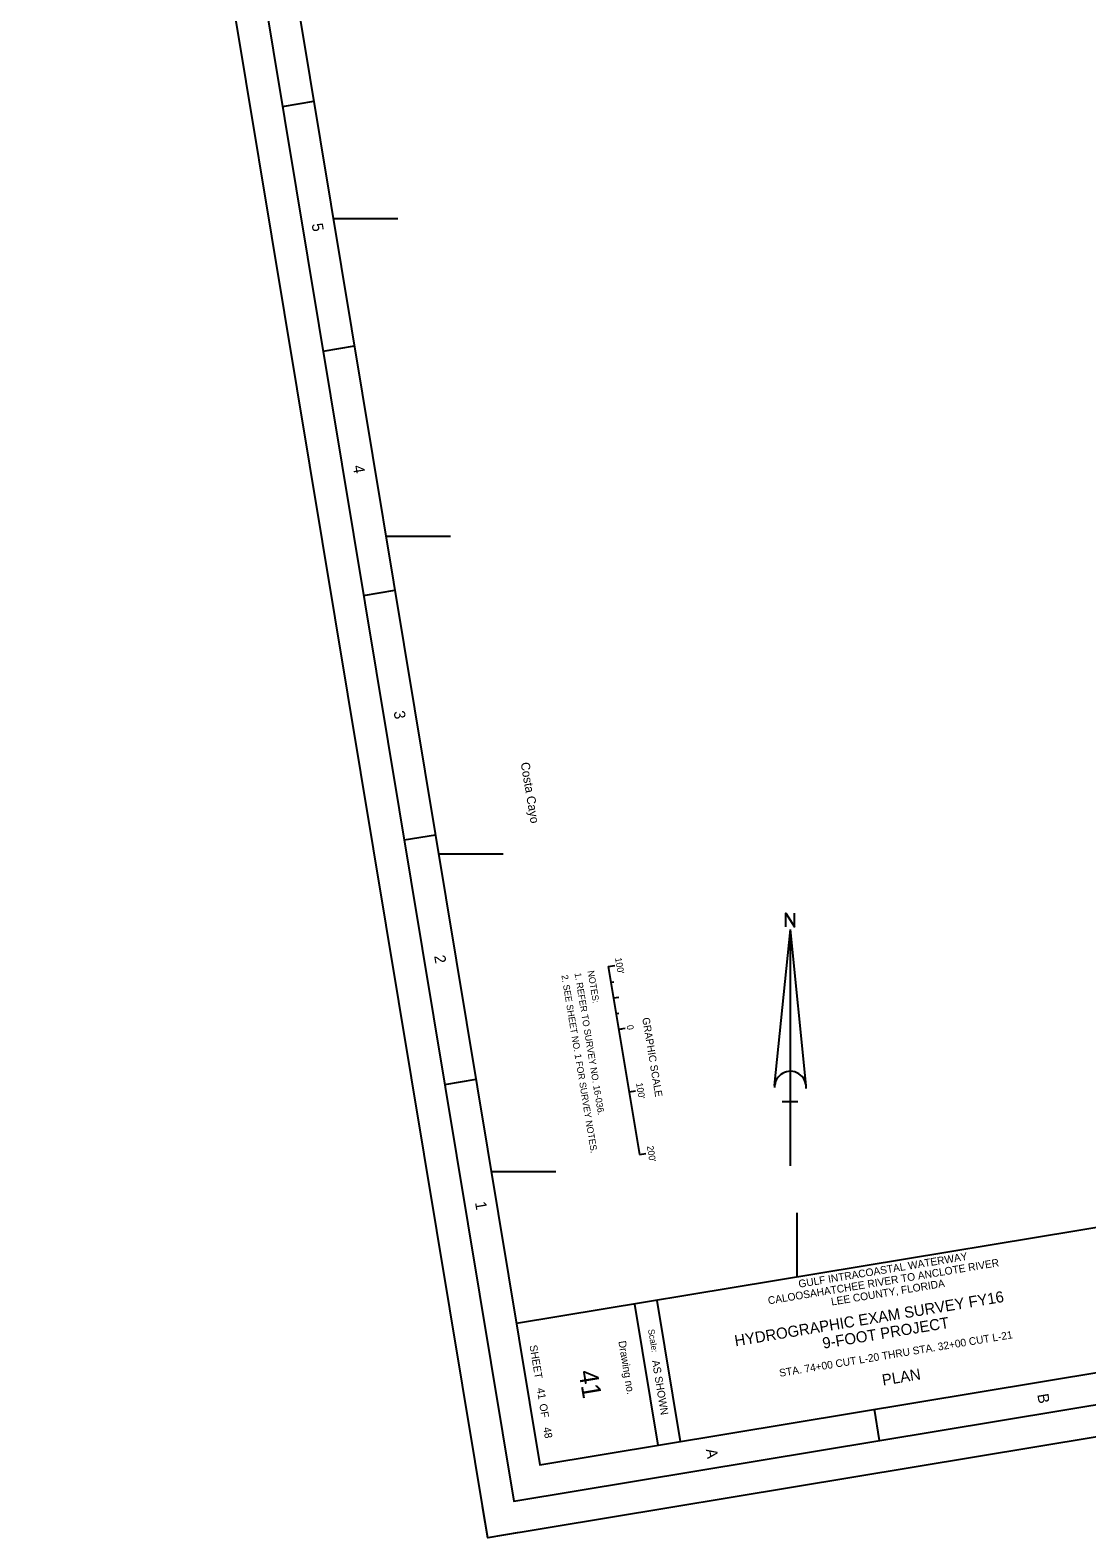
# Model space of a CAD drawing. Extents: x 574793 to 578867, y 860923 to 865820.
# Drawn here: x 574793 to 576456, y 860923 to 863296 of the extents above; entities that cross this region are included whole.
import ezdxf

# ---------------------------------------------------------------- set-up
doc = ezdxf.new("R2010")
doc.units = 0
for name, color, linetype in [('G-ANNO-NPLT', 7, 'Continuous'), ('G-ANNO-TEXT-DRWG', 7, 'Continuous'), ('G-ANNO-TEXT-PROJ', 7, 'Continuous'), ('G-ANNO-TEXT-TTLB', 7, 'Continuous'), ('G-ANNO-TTLB', 7, 'Continuous'), ('V-ANNO-NOTE', 7, 'Continuous'), ('V-ANNO-SYMB', 7, 'Continuous'), ('V-SITE-IDEN', 7, 'Continuous'), ('V-TOPO-COOR-STAT', 7, 'Continuous')]:
    doc.layers.add(name, color=color, linetype=linetype)

msp = doc.modelspace()

# ---------------------------------------------------------------- linework, layer by layer
at = {"layer": 'G-ANNO-NPLT'}
msp.add_lwpolyline([(578147.3, 865820.4), (578867.1, 861479.7), (575512.9, 860923.5), (574793.1, 865264.2)], close=True, dxfattribs=at)
msp.add_lwpolyline([(575562.2, 860931.5), (575512.9, 860923.3), (575504.7, 860972.7)], dxfattribs=at)
at = {"layer": 'G-ANNO-TTLB'}
for p, q in [((575190, 863176), (575239.4, 863184.2)), ((575253.9, 862791.2), (575303.2, 862799.4)), ((575317.7, 862406.5), (575367, 862414.7)), ((575381.5, 862021.8), (575430.8, 862029.9)), ((578715.2, 861784), (575558.4, 861260.5)), ((575445.3, 861637), (575494.6, 861645.2)), ((575743.9, 861291.2), (575780.7, 861069.3)), ((575779.1, 861297.1), (575815.9, 861075.1)), ((576129.5, 861076.4), (576121.3, 861125.7))]:
    msp.add_line(p, q, dxfattribs=at)
for points in [[(574850.6, 865223), (575554, 860981), (578809.6, 861520.8), (578106.1, 865762.9)], [(578752.1, 861562), (578077.2, 865631.4), (574920.4, 865107.9), (575595.2, 861038.5)]]:
    msp.add_lwpolyline(points, close=True, dxfattribs=at)
at = {"layer": 'V-ANNO-NOTE'}
for p, q in [((575702.5, 861822.5), (575712.8, 861824.2)), ((575702.5, 861822.5), (575751.6, 861526.5)), ((575706.6, 861797.8), (575711.4, 861798.6)), ((575710.7, 861773.1), (575719.1, 861774.5)), ((575714.8, 861748.5), (575719.5, 861749.3)), ((575718.9, 861723.8), (575729.2, 861725.5)), ((575718.9, 861723.8), (575729.2, 861725.5)), ((575718.9, 861723.8), (575723.8, 861724.6)), ((575735.3, 861625.2), (575745.6, 861626.9)), ((575751.6, 861526.5), (575761.9, 861528.2))]:
    msp.add_line(p, q, dxfattribs=at)
at = {"layer": 'V-ANNO-SYMB'}
for p, q in [((575964.4, 861635.3), (575989.1, 861881)), ((575989.1, 861508.7), (575989.1, 861881)), ((576013.8, 861635.3), (575989.1, 861881)), ((576000.8, 861609.3), (575976, 861609.3))]:
    msp.add_line(p, q, dxfattribs=at)
msp.add_lwpolyline([(575982.2, 861885), (575982.2, 861906.7), (575995.7, 861885), (575995.7, 861906.7)], dxfattribs=at)
msp.add_arc((575989.1, 861632.8), 24.8, 355.2984, 182.0673, dxfattribs=at)
at = {"layer": 'V-TOPO-COOR-STAT'}
for p, q in [((575269.9, 863000), (575371.3, 863000)), ((575352.8, 862500), (575454.2, 862500)), ((575435.7, 862000), (575537.1, 862000)), ((575518.7, 861500), (575620, 861500)), ((576000, 861333.7), (576000, 861435.1))]:
    msp.add_line(p, q, dxfattribs=at)

# ---------------------------------------------------------------- texts
at = {"layer": 'G-ANNO-TEXT-DRWG'}
for s, height, rotation, p in [('STA. 74+00 CUT L-20 THRU STA. 32+00 CUT L-21', 12, 9.4155, (575972.7, 861176.7)), ('PLAN', 17.5, 9.4155, (576134.9, 861162.9)), ('41', 30, 279.4155, (575655.8, 861185.2)), (' 41          48', 12, 279.4155, (575589.3, 861162.7))]:
    msp.add_text(s, height=height, rotation=rotation, dxfattribs=at).set_placement(p)
at = {"layer": 'G-ANNO-TEXT-PROJ'}
for s, height, p in [('CALOOSAHATCHEE RIVER TO ANCLOTE RIVER', 12, (575954.9, 861290.7)), ('GULF INTRACOASTAL WATERWAY', 12, (576002.9, 861316.9)), ('HYDROGRAPHIC EXAM SURVEY FY16', 17.5, (575902.8, 861224.6)), ('LEE COUNTY, FLORIDA', 12, (576054.2, 861288.9)), ('9-FOOT PROJECT', 17.5, (576041.1, 861220.9))]:
    msp.add_text(s, height=height, rotation=9.4155, dxfattribs=at).set_placement(p)
at = {"layer": 'G-ANNO-TEXT-TTLB'}
for s, height, p in [('Scale:', 10, (575765.1, 861251)), ('SHEET         OF', 12, (575578.8, 861225.9)), ('Drawing no.', 12, (575718.5, 861232.5)), ('AS SHOWN', 12, (575771.3, 861202.1))]:
    msp.add_text(s, height=height, rotation=279.4155, dxfattribs=at).set_placement(p)
at = {"layer": 'G-ANNO-TTLB'}
for s, p in [('5', (575235.9, 862990.9)), ('4', (575300.8, 862610.2)), ('3', (575364.9, 862223.6)), ('2', (575428.6, 861839.1)), ('1', (575492.9, 861451.2)), ('B', (576377.6, 861148.9)), ('A', (575856, 861062.4))]:
    msp.add_text(s, height=17.5, rotation=279.4155, dxfattribs=at).set_placement(p)
at = {"layer": 'V-ANNO-NOTE'}
for s, height, p in [("100'", 10.42, (575713.3, 861835.7)), ('2. SEE SHEET NO. 1 FOR SURVEY NOTES.', 10.416, (575628.9, 861808.5)), ('1. REFER TO SURVEY NO. 16-036.', 10.416, (575649.5, 861811.9)), ('NOTES:', 10.42, (575670, 861815.3)), ('GRAPHIC SCALE', 11.666, (575756, 861741.3)), ('0', 10.4, (575731.5, 861729.7)), ("100'", 10.42, (575746.3, 861638.8)), ("200'", 10.42, (575763.3, 861539.7))]:
    msp.add_text(s, height=height, rotation=279.4155, dxfattribs=at).set_placement(p)
at = {"layer": 'V-SITE-IDEN'}
msp.add_text('Costa Cayo', height=13.92, rotation=279.4155, dxfattribs=at).set_placement((575564.8, 862142.9))

doc.saveas('drawing.dxf')
